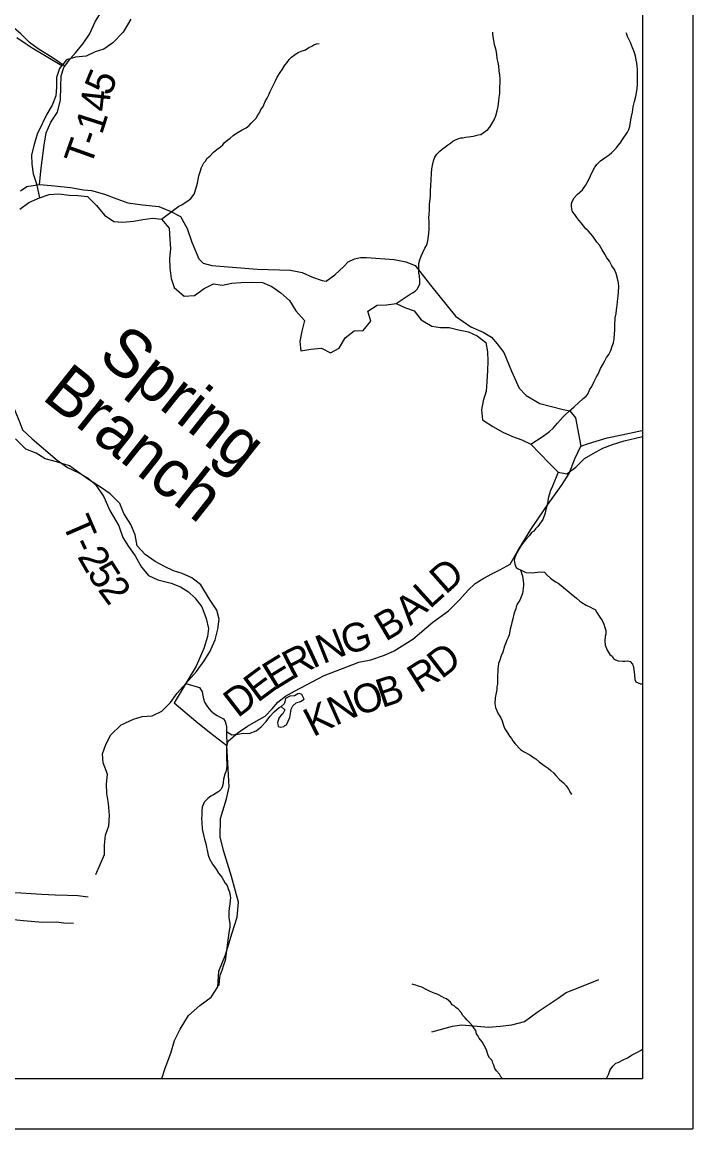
# Model space of a CAD drawing. Extents: x 0 to 34, y 0 to 22.
# Drawn here: x 7.671 to 9, y 14 to 16.191 of the extents above; entities that cross this region are included whole.
import ezdxf

# ---------------------------------------------------------------- set-up
doc = ezdxf.new("R2010")
doc.units = 0
for name, color, linetype in [('GM_X_County_Road', 7, 'Continuous'), ('GM_X_County_Road_Text', 7, 'Continuous'), ('GM_X_Major_River', 7, 'Continuous'), ('GM_X_Minor_Lake', 7, 'Continuous'), ('GM_X_Minor_River', 7, 'Continuous'), ('GM_X_Minor_River_Text', 7, 'Continuous'), ('GM_X_Township_Road', 7, 'Continuous'), ('GM_X_Township_Road_Text', 7, 'Continuous'), ('SH_Data', 7, 'Continuous')]:
    doc.layers.add(name, color=color, linetype=linetype)

msp = doc.modelspace()

# ---------------------------------------------------------------- linework, layer by layer
at = {"layer": 'GM_X_County_Road'}
for points in [[(7.668, 15.8575), (7.6806, 15.8662), (7.706, 15.87), (7.7288, 15.8681), (7.7672, 15.8643), (7.793, 15.8597), (7.8089, 15.8582), (7.8344, 15.851), (7.8587, 15.8415), (7.8807, 15.8339), (7.9099, 15.83), (7.9422, 15.8266), (7.9643, 15.8171), (7.9848, 15.8065), (7.9984, 15.7826), (8.0075, 15.7556), (8.0158, 15.7355), (8.0211, 15.7229), (8.0302, 15.7142), (8.047, 15.7093), (8.1366, 15.7024), (8.203, 15.7001), (8.2262, 15.6959), (8.2463, 15.6868), (8.2657, 15.6799), (8.2737, 15.6788), (8.2908, 15.691), (8.3083, 15.7077), (8.317, 15.7168), (8.3295, 15.7228), (8.3413, 15.7255), (8.3535, 15.7251), (8.4082, 15.7213), (8.4313, 15.7168), (8.4499, 15.7095), (8.4803, 15.6708), (8.5296, 15.6093), (8.5604, 15.588), (8.5847, 15.5774), (8.601, 15.5675), (8.6124, 15.5546), (8.6253, 15.5375), (8.6404, 15.5003), (8.6556, 15.4668), (8.6696, 15.4524), (8.6966, 15.4365), (8.7429, 15.4243), (8.7566, 15.4216), (8.7672, 15.408), (8.7778, 15.3521)], [(7.9479, 14.1), (7.9548, 14.1203), (7.9658, 14.1499), (7.9734, 14.1753), (7.9841, 14.1973), (8.0012, 14.2246), (8.0236, 14.2444), (8.0461, 14.2607), (8.059, 14.2812), (8.0613, 14.3123), (8.0742, 14.3446), (8.0872, 14.3883), (8.0971, 14.4194), (8.0998, 14.449), (8.0858, 14.4995), (8.0703, 14.5511), (8.0635, 14.5782), (8.0642, 14.6145), (8.0764, 14.6537), (8.0814, 14.6776), (8.0788, 14.7247), (8.0769, 14.7592), (8.0792, 14.7679), (8.0993, 14.785), (8.1179, 14.7975), (8.135, 14.8074), (8.1525, 14.8173), (8.1666, 14.8317), (8.178, 14.8446), (8.1928, 14.8571), (8.2111, 14.8666), (8.2472, 14.8856), (8.2696, 14.8974), (8.3144, 14.9152), (8.3383, 14.9243), (8.3619, 14.9288), (8.3889, 14.9383), (8.4086, 14.9467), (8.4291, 14.9596), (8.4455, 14.9695), (8.485, 15.0032), (8.5162, 15.0256), (8.5375, 15.0473), (8.5546, 15.067), (8.569, 15.0799), (8.5857, 15.0902), (8.6017, 15.0993), (8.6188, 15.1073), (8.6382, 15.1179), (8.653, 15.1445), (8.6793, 15.1866), (8.6945, 15.209), (8.7127, 15.2363), (8.7397, 15.2739), (8.755, 15.2975), (8.7664, 15.3267), (8.7778, 15.3521), (8.793, 15.3571), (8.8302, 15.3685), (8.8591, 15.3745), (8.8986, 15.3829), (8.9, 15.383)]]:
    msp.add_lwpolyline(points, dxfattribs=at)
at = {"layer": 'GM_X_Major_River'}
for points in [[(7.6666, 15.8213), (7.6848, 15.8341), (7.706, 15.8439), (7.725, 15.8499), (7.7439, 15.8514), (7.7643, 15.8491), (7.7817, 15.8483), (7.8006, 15.8459), (7.8188, 15.8284), (7.8346, 15.8094), (7.8527, 15.7965), (7.8701, 15.7957), (7.8928, 15.7971), (7.9103, 15.8009), (7.93, 15.8031), (7.9474, 15.8015), (7.9624, 15.7833), (7.9639, 15.7613), (7.9653, 15.7431), (7.963, 15.7226), (7.9637, 15.7052), (7.9667, 15.6839), (7.9727, 15.6657), (7.9923, 15.649), (8.0127, 15.6504), (8.0317, 15.664), (8.0507, 15.6731), (8.0681, 15.6708), (8.087, 15.6745), (8.1044, 15.676), (8.1249, 15.6767), (8.1476, 15.6758), (8.1657, 15.6682), (8.1838, 15.6553), (8.2012, 15.64), (8.2132, 15.6195), (8.2306, 15.6005), (8.2252, 15.5793), (8.2214, 15.5588), (8.2236, 15.5406), (8.2433, 15.5436), (8.2645, 15.5458), (8.2819, 15.5367), (8.2993, 15.5457), (8.3115, 15.5662), (8.3289, 15.5805), (8.3471, 15.5812), (8.3623, 15.5994), (8.3563, 15.6191), (8.3745, 15.6312), (8.3934, 15.6319), (8.4124, 15.6342)], [(8.4124, 15.6342), (8.4305, 15.6258), (8.4479, 15.6197), (8.4615, 15.6022), (8.4826, 15.5892), (8.5, 15.5869), (8.5174, 15.5869), (8.5356, 15.5823), (8.5553, 15.5784), (8.5726, 15.57), (8.59, 15.5571), (8.593, 15.5389), (8.5937, 15.5199), (8.5929, 15.5017), (8.592, 15.479), (8.5905, 15.4608), (8.5844, 15.4418), (8.5813, 15.4236), (8.5835, 15.4039), (8.6039, 15.391), (8.6235, 15.3795), (8.6424, 15.3711), (8.6613, 15.3643), (8.6787, 15.3559), (8.6968, 15.3376), (8.7157, 15.3178), (8.733, 15.3004), (8.7504, 15.2973), (8.7679, 15.3101), (8.7854, 15.3275), (8.8028, 15.3373), (8.8218, 15.3479), (8.8407, 15.3554), (8.8642, 15.3622), (8.8862, 15.3675), (8.9, 15.3709)]]:
    msp.add_lwpolyline(points, dxfattribs=at)
at = {"layer": 'GM_X_Minor_Lake'}
for points in [[(8.23, 14.8508), (8.2255, 14.8599), (8.2206, 14.8618), (8.2175, 14.8614), (8.2107, 14.8573), (8.2017, 14.8565), (8.1933, 14.852), (8.1914, 14.8455), (8.1903, 14.8417), (8.1846, 14.8364)], [(8.1846, 14.8364), (8.1918, 14.8296), (8.188, 14.822), (8.1854, 14.8198), (8.1808, 14.8148), (8.177, 14.8046), (8.1782, 14.797), (8.1835, 14.7952), (8.1895, 14.7967), (8.1918, 14.7989), (8.1948, 14.8001), (8.1982, 14.8073), (8.2013, 14.8145), (8.2035, 14.8262), (8.2043, 14.8311), (8.2077, 14.8376), (8.2141, 14.8436), (8.2228, 14.8463), (8.23, 14.8508)]]:
    msp.add_lwpolyline(points, dxfattribs=at)
at = {"layer": 'GM_X_Minor_River'}
for points in [[(7.8865, 16.1976), (7.8713, 16.1719), (7.8508, 16.1507), (7.8333, 16.1379), (7.8159, 16.1326), (7.7985, 16.1243), (7.7773, 16.1221), (7.7591, 16.1168), (7.7454, 16.0994), (7.7393, 16.082), (7.7393, 16.063), (7.7384, 16.0456), (7.7308, 16.0274), (7.7202, 16.0092), (7.711, 15.9903), (7.7011, 15.9698), (7.695, 15.9494), (7.6896, 15.9289), (7.6903, 15.91), (7.6933, 15.891), (7.7, 15.8712), (7.706, 15.8439)], [(7.75, 16.1052), (7.6911, 16.14), (7.6771, 16.1491), (7.6608, 16.1604)], [(8.4124, 15.6342), (8.4403, 15.6527), (8.4449, 15.6557), (8.4499, 15.659), (8.4541, 15.6627), (8.4564, 15.6673), (8.4592, 15.6733), (8.4593, 15.6801), (8.4583, 15.6889), (8.4573, 15.6953), (8.4571, 15.7022), (8.4573, 15.7136), (8.4593, 15.7211), (8.4621, 15.7279), (8.4652, 15.7351), (8.4692, 15.7441), (8.4723, 15.749), (8.4743, 15.7551), (8.4755, 15.7623), (8.4769, 15.7733), (8.4774, 15.782), (8.4775, 15.7888), (8.4773, 15.7968), (8.477, 15.8044), (8.4775, 15.8109), (8.4781, 15.82), (8.4786, 15.831), (8.4796, 15.8408), (8.4801, 15.848), (8.4806, 15.8575), (8.4808, 15.8674), (8.4814, 15.8792), (8.482, 15.8921), (8.4829, 15.9008), (8.4846, 15.911), (8.4862, 15.9171), (8.4886, 15.9239), (8.4929, 15.9302), (8.4987, 15.9358), (8.5041, 15.9403), (8.5083, 15.9433), (8.514, 15.9477), (8.5198, 15.9518), (8.5248, 15.9555), (8.5297, 15.9585), (8.5343, 15.9603), (8.5404, 15.9621), (8.5446, 15.9624), (8.5499, 15.9635), (8.5556, 15.9645), (8.5602, 15.9652), (8.5655, 15.9659), (8.5746, 15.968), (8.5803, 15.969), (8.5849, 15.972), (8.5895, 15.9757), (8.5941, 15.9787), (8.5976, 15.9836), (8.6019, 15.9899), (8.6066, 15.9982), (8.6094, 16.0062), (8.6122, 16.016), (8.6142, 16.0247), (8.6156, 16.0357), (8.6165, 16.0425), (8.6173, 16.0505), (8.6178, 16.0569), (8.6182, 16.0782), (8.6176, 16.0873), (8.6166, 16.0945), (8.6157, 16.1048), (8.6146, 16.1113), (8.6125, 16.1193), (8.6119, 16.1273), (8.6101, 16.1357), (8.608, 16.1444), (8.6052, 16.1582), (8.6042, 16.1631), (8.6039, 16.1677), (8.604, 16.1719)], [(8.8906, 16.0808), (8.8903, 16.0877), (8.8901, 16.0979), (8.8895, 16.104), (8.8892, 16.1101), (8.8878, 16.1162), (8.8868, 16.1215), (8.885, 16.1288), (8.8828, 16.1345), (8.8803, 16.1406), (8.8763, 16.151), (8.873, 16.1579), (8.8708, 16.1632), (8.869, 16.1678), (8.8679, 16.1705)], [(7.9474, 15.8015), (7.9816, 15.8268), (7.9877, 15.8297), (7.9942, 15.8342), (7.9996, 15.8379), (8.0058, 15.8423), (8.012, 15.851), (8.0163, 15.8634), (8.0188, 15.8729), (8.02, 15.8797), (8.0213, 15.8873), (8.0237, 15.8948), (8.0265, 15.9039), (8.0312, 15.9129), (8.0351, 15.917), (8.0374, 15.9212), (8.0436, 15.9268), (8.0502, 15.9339), (8.0571, 15.9394), (8.0644, 15.9446), (8.069, 15.9484), (8.0717, 15.9525), (8.0786, 15.9585), (8.0836, 15.9618), (8.0894, 15.967), (8.0963, 15.9715), (8.107, 15.9785), (8.115, 15.9825), (8.1212, 15.987), (8.125, 15.9915), (8.1289, 15.9956), (8.1358, 16.0023), (8.1378, 16.0065), (8.1417, 16.0117), (8.1441, 16.0185), (8.1479, 16.0234), (8.1503, 16.0275), (8.1531, 16.0355), (8.1566, 16.0411), (8.1597, 16.0475), (8.1625, 16.0543), (8.1688, 16.0663), (8.1723, 16.0739), (8.1766, 16.0822), (8.1825, 16.0916), (8.1871, 16.0983), (8.1918, 16.1066), (8.1965, 16.1118), (8.2, 16.1175), (8.205, 16.1219), (8.2127, 16.1283), (8.218, 16.1316), (8.2241, 16.1338), (8.2287, 16.1352), (8.2329, 16.1367), (8.2394, 16.1411), (8.2451, 16.1441), (8.2494, 16.1463), (8.2554, 16.1484), (8.2596, 16.1495)], [(8.6787, 15.3559), (8.7035, 15.3718), (8.7108, 15.377), (8.7162, 15.3811), (8.7235, 15.3874), (8.7316, 15.3976), (8.7424, 15.4095), (8.747, 15.4136), (8.7551, 15.4211), (8.7651, 15.4297), (8.7736, 15.4379), (8.7828, 15.4465), (8.7886, 15.4509), (8.7917, 15.455), (8.7957, 15.4645), (8.7991, 15.4686), (8.8035, 15.4788), (8.809, 15.4893), (8.8121, 15.4946), (8.8168, 15.5059), (8.8219, 15.5134), (8.8254, 15.5209), (8.829, 15.5273), (8.8336, 15.5333), (8.8372, 15.5413), (8.8404, 15.5499), (8.8427, 15.5564), (8.844, 15.5647), (8.8446, 15.5742), (8.8451, 15.5814), (8.8452, 15.5905), (8.8463, 15.6057), (8.8479, 15.6148), (8.8488, 15.622), (8.8497, 15.6265), (8.8501, 15.6307), (8.8506, 15.6386), (8.8515, 15.6439), (8.8519, 15.6489), (8.8528, 15.6572), (8.8534, 15.6671), (8.8524, 15.6754), (8.8507, 15.6838), (8.8478, 15.6938), (8.8449, 15.7014), (8.8397, 15.7091), (8.8346, 15.7179), (8.8294, 15.7248), (8.8254, 15.7321), (8.8206, 15.7405), (8.8151, 15.7498), (8.8099, 15.7559), (8.8058, 15.7617), (8.8018, 15.7678), (8.7973, 15.7732), (8.7925, 15.7782), (8.788, 15.7825), (8.7836, 15.7879), (8.7787, 15.794), (8.7739, 15.7991), (8.7702, 15.8048), (8.7662, 15.8106), (8.7617, 15.816), (8.7603, 15.8221), (8.7593, 15.8274), (8.7593, 15.8316), (8.7609, 15.8365), (8.7648, 15.8433), (8.771, 15.8504), (8.776, 15.8549), (8.7814, 15.8593), (8.7872, 15.868), (8.7923, 15.877), (8.7974, 15.8872), (8.8014, 15.8954), (8.8057, 15.9045), (8.8103, 15.9101), (8.8169, 15.9168), (8.8234, 15.9213), (8.828, 15.9246), (8.8341, 15.9287), (8.8395, 15.9332), (8.8434, 15.9373), (8.848, 15.9421), (8.8523, 15.9474), (8.8558, 15.9515), (8.8608, 15.9594), (8.8702, 15.9737), (8.8733, 15.9789), (8.8753, 15.985), (8.8761, 15.9892), (8.8774, 15.9979), (8.8787, 16.0047), (8.8803, 16.0134), (8.882, 16.0236), (8.8845, 16.0346), (8.8869, 16.044), (8.8882, 16.0516), (8.8895, 16.0603), (8.8904, 16.0687), (8.8906, 16.0808)], [(7.8176, 14.5036), (7.8344, 14.543), (7.8345, 14.5619), (7.8368, 14.5816), (7.8429, 14.5998), (7.8445, 14.6203), (7.8423, 14.6446), (7.8393, 14.6643), (7.8386, 14.6833), (7.8402, 14.7022), (7.8319, 14.725), (7.8305, 14.7424), (7.8374, 14.7614), (7.8473, 14.7803), (7.8678, 14.8), (7.892, 14.8113), (7.9094, 14.8165), (7.9291, 14.818), (7.9481, 14.827), (7.9655, 14.8444), (7.9785, 14.8626), (7.9959, 14.8822), (8.0165, 14.9057), (8.0317, 14.9269), (8.0431, 14.9443), (8.0537, 14.9685), (8.0591, 14.9897), (8.0614, 15.0095), (8.057, 15.0269), (8.0426, 15.0489), (8.0253, 15.0771), (8.0072, 15.0908), (7.9883, 15.0999), (7.9709, 15.1053), (7.9535, 15.1137), (7.9346, 15.1236), (7.915, 15.1373), (7.8992, 15.1548), (7.8954, 15.176), (7.8864, 15.1965), (7.8729, 15.2185), (7.8646, 15.2383), (7.8457, 15.2573), (7.8284, 15.2695), (7.8049, 15.2847), (7.7868, 15.2969), (7.7649, 15.3129), (7.7392, 15.3205), (7.7173, 15.3267), (7.6991, 15.3381), (7.6787, 15.3457), (7.6583, 15.3663)], [(8.733, 15.3004), (8.7218, 15.2724), (8.7183, 15.2641), (8.7155, 15.2558), (8.7134, 15.2479), (8.7121, 15.238), (8.7081, 15.2236), (8.7076, 15.2191), (8.7029, 15.2066), (8.6994, 15.2021), (8.6932, 15.1931), (8.6881, 15.1879), (8.6847, 15.1838), (8.6801, 15.1808), (8.6766, 15.1752), (8.6692, 15.1673), (8.6626, 15.1591), (8.6568, 15.1501), (8.6521, 15.1418), (8.6494, 15.1361), (8.6474, 15.1312), (8.6458, 15.1263), (8.6471, 15.1179), (8.6501, 15.1118), (8.6542, 15.1087), (8.6587, 15.1071), (8.6639, 15.104), (8.6688, 15.1016), (8.6817, 15.1007), (8.6923, 15.1024), (8.701, 15.103), (8.706, 15.1025), (8.7112, 15.0967), (8.7179, 15.0902), (8.728, 15.0832), (8.7332, 15.0804), (8.7388, 15.0758), (8.7474, 15.0684), (8.7541, 15.0637), (8.7597, 15.0591), (8.7653, 15.0541), (8.7698, 15.051), (8.7762, 15.0452), (8.7803, 15.0424), (8.7889, 15.037), (8.7972, 15.033), (8.802, 15.0303), (8.8065, 15.0283), (8.8099, 15.0226), (8.8146, 15.0153), (8.8202, 15.0064), (8.8235, 14.9996), (8.8256, 14.9927), (8.8274, 14.9866), (8.8273, 14.9794), (8.8264, 14.9748), (8.8259, 14.9661), (8.8265, 14.9577), (8.8301, 14.9482), (8.8353, 14.9394), (8.8398, 14.9359), (8.8427, 14.9313), (8.8468, 14.9285), (8.8517, 14.9265), (8.8612, 14.926), (8.8654, 14.9263), (8.8714, 14.927), (8.8756, 14.9254), (8.8804, 14.9204), (8.8826, 14.915), (8.8842, 14.8983), (8.8848, 14.8895), (8.887, 14.8853), (8.8915, 14.883), (8.8964, 14.8814), (8.9, 14.881)], [(8.6587, 15.1071), (8.6626, 15.0941), (8.6629, 15.0896), (8.664, 15.085), (8.6647, 15.0801), (8.6646, 15.0759), (8.6641, 15.0709), (8.6624, 15.0603), (8.6573, 15.0471), (8.6522, 15.0392), (8.6502, 15.034), (8.6494, 15.0298), (8.6466, 15.0234), (8.6454, 15.0192), (8.6433, 15.0098), (8.6417, 15.003), (8.6401, 14.9965), (8.6384, 14.9897), (8.6363, 14.978), (8.6344, 14.9731), (8.6316, 14.9674), (8.6288, 14.9603), (8.6269, 14.9557), (8.6236, 14.944), (8.6205, 14.9369), (8.6177, 14.9278), (8.6149, 14.9218), (8.6144, 14.9153), (8.6139, 14.9108), (8.6138, 14.9047), (8.6133, 14.8982), (8.613, 14.8804), (8.6118, 14.8751), (8.6117, 14.8694), (8.6101, 14.8634), (8.6084, 14.8535), (8.6078, 14.8425), (8.6092, 14.8345), (8.6143, 14.8219), (8.6187, 14.815), (8.622, 14.8081), (8.6249, 14.7989), (8.6278, 14.7921), (8.6329, 14.784), (8.637, 14.7778), (8.6407, 14.7732), (8.6436, 14.7682), (8.6477, 14.7625), (8.6585, 14.7513), (8.6648, 14.747), (8.6769, 14.7407), (8.6821, 14.7368), (8.6888, 14.7326), (8.6955, 14.7267), (8.7053, 14.7194), (8.7131, 14.7143), (8.7187, 14.7096), (8.7243, 14.7046), (8.7284, 14.6996), (8.7358, 14.6919), (8.7437, 14.6853), (8.7493, 14.6795), (8.7537, 14.6726), (8.7577, 14.6653), (8.7595, 14.662)], [(7.9959, 14.8822), (8.0224, 14.874), (8.0279, 14.8656), (8.0293, 14.8583), (8.0303, 14.8518), (8.0329, 14.845), (8.0388, 14.8358), (8.0451, 14.8277), (8.0525, 14.8215), (8.0578, 14.8187), (8.0623, 14.8156), (8.0705, 14.8117), (8.0735, 14.8067), (8.0749, 14.8017), (8.076, 14.7964), (8.0763, 14.7918), (8.0762, 14.7869), (8.0764, 14.7808), (8.0763, 14.7747), (8.0766, 14.7687), (8.0762, 14.7474), (8.0765, 14.7398), (8.0763, 14.7314), (8.0766, 14.7235), (8.0769, 14.7189), (8.0764, 14.7132), (8.0751, 14.7068), (8.0728, 14.7023), (8.0703, 14.6924), (8.0698, 14.6856), (8.069, 14.6811), (8.0674, 14.6765), (8.0651, 14.672), (8.0608, 14.6683), (8.0555, 14.6646), (8.0501, 14.6616), (8.0451, 14.6591), (8.039, 14.6542), (8.032, 14.6468), (8.0277, 14.637), (8.0272, 14.6297), (8.027, 14.6203), (8.0269, 14.6153), (8.0275, 14.6062), (8.0281, 14.5944), (8.0291, 14.5876), (8.0312, 14.5792), (8.0323, 14.5738), (8.0341, 14.5689), (8.0359, 14.5624), (8.0365, 14.5574), (8.0376, 14.5521), (8.04, 14.5418), (8.0426, 14.5349), (8.0484, 14.5242), (8.0555, 14.5142), (8.0606, 14.5061), (8.0669, 14.4981), (8.0702, 14.4927), (8.0735, 14.4866), (8.0772, 14.4819), (8.0798, 14.4754), (8.0816, 14.4709), (8.0826, 14.4659), (8.0837, 14.4617), (8.084, 14.4575), (8.0835, 14.4526), (8.0827, 14.4458), (8.0814, 14.4371), (8.0809, 14.4299), (8.0808, 14.4242), (8.081, 14.4177), (8.0824, 14.4108), (8.0827, 14.4063), (8.0826, 14.3994), (8.0817, 14.3926), (8.0805, 14.3881)], [(8.0762, 14.7868), (8.087, 14.78), (8.0983, 14.7815), (8.11, 14.7834), (8.1214, 14.7827), (8.135, 14.788), (8.1449, 14.7963), (8.1547, 14.8065), (8.1623, 14.8164), (8.1706, 14.8258), (8.1804, 14.8345), (8.1846, 14.8364)], [(8.0805, 14.3881), (8.0736, 14.3334), (8.0705, 14.3239), (8.0671, 14.3137), (8.063, 14.3039), (8.0618, 14.294), (8.0607, 14.2838), (8.0603, 14.2842)], [(8.6228, 14.1), (8.6198, 14.1033), (8.6168, 14.1083), (8.6113, 14.1149), (8.608, 14.1195), (8.6054, 14.126), (8.6036, 14.1298), (8.6025, 14.1351), (8.597, 14.1409), (8.5944, 14.1455), (8.5922, 14.152), (8.5912, 14.1566), (8.5868, 14.1654), (8.5827, 14.1723), (8.5794, 14.1762), (8.5768, 14.1796), (8.5746, 14.1838), (8.5717, 14.1884), (8.5699, 14.1945), (8.5677, 14.1984), (8.5625, 14.2049), (8.5573, 14.2103), (8.5528, 14.2153), (8.5491, 14.2196), (8.5439, 14.2254), (8.5417, 14.2296), (8.535, 14.2369), (8.5302, 14.24), (8.5272, 14.2435), (8.5234, 14.2458), (8.5201, 14.2512), (8.5119, 14.2574), (8.5078, 14.259), (8.5036, 14.2617), (8.4973, 14.2645), (8.4935, 14.2668), (8.4875, 14.2688), (8.4841, 14.27), (8.4785, 14.2724), (8.4728, 14.2752), (8.4631, 14.2803), (8.4582, 14.2822), (8.4548, 14.2834), (8.451, 14.2846), (8.4476, 14.2855), (8.4439, 14.2863)], [(8.8285, 14.1), (8.8296, 14.101), (8.8331, 14.1078), (8.8363, 14.1168), (8.8414, 14.1243), (8.8471, 14.1299), (8.8517, 14.1317), (8.862, 14.1365), (8.8708, 14.1405), (8.8796, 14.1468), (8.8888, 14.1509), (8.8965, 14.1553), (8.9, 14.1576)]]:
    msp.add_lwpolyline(points, dxfattribs=at)
at = {"layer": 'GM_X_Township_Road'}
for points in [[(7.7559, 16.1046), (7.7328, 16.1199), (7.7028, 16.1385), (7.6858, 16.1514), (7.6687, 16.1685), (7.6558, 16.1795), (7.6379, 16.1924), (7.6266, 16.2015), (7.6137, 16.2171), (7.603, 16.2388), (7.5913, 16.2642), (7.5784, 16.2795), (7.5746, 16.284), (7.5611, 16.2941), (7.5484, 16.3037), (7.5441, 16.3069)], [(7.706, 15.87), (7.7091, 15.9026), (7.7148, 15.9478), (7.719, 15.9721), (7.7285, 15.9934), (7.7411, 16.0135), (7.7476, 16.0374), (7.7483, 16.064), (7.7484, 16.0849), (7.7537, 16.1016), (7.7559, 16.1046), (7.7663, 16.1187), (7.7773, 16.1309), (7.7921, 16.1491), (7.805, 16.1677), (7.8168, 16.1931), (7.8281, 16.2111)], [(7.612, 15.4947), (7.6267, 15.4872), (7.6328, 15.4648), (7.646, 15.444), (7.6559, 15.4242), (7.6676, 15.3965), (7.6718, 15.3843), (7.6915, 15.3661), (7.7405, 15.3239), (7.7614, 15.3095), (7.7826, 15.2996), (7.8024, 15.2882), (7.8157, 15.2758)], [(7.8157, 15.2758), (7.8179, 15.2738), (7.8335, 15.2514), (7.8452, 15.2244), (7.8627, 15.1944), (7.8706, 15.1712), (7.882, 15.1534), (7.8953, 15.1344), (7.9078, 15.112), (7.9218, 15.0957), (7.9401, 15.0869), (7.9666, 15.0805), (7.9852, 15.0732), (8.0012, 15.0634), (8.0137, 15.0516), (8.0274, 15.0337), (8.0361, 15.0106), (8.0406, 14.9908), (8.0387, 14.9749), (8.0315, 14.951), (8.0163, 14.916), (7.9965, 14.883), (7.9725, 14.8439), (8.0154, 14.8074), (8.0427, 14.7858), (8.0769, 14.7592)], [(7.5997, 14.4488), (7.6062, 14.4561), (7.6169, 14.4645), (7.6257, 14.4683), (7.6337, 14.4691), (7.6689, 14.4672), (7.6895, 14.466), (7.7102, 14.4645), (7.7366, 14.4633), (7.7614, 14.4626), (7.7818, 14.4621), (7.8021, 14.4597)], [(7.6544, 14.4148), (7.6739, 14.4125), (7.7117, 14.409), (7.7389, 14.4098), (7.7538, 14.4083), (7.7729, 14.4075)], [(8.4827, 14.192), (8.5241, 14.2035), (8.5425, 14.2058), (8.5953, 14.2013), (8.6183, 14.2036), (8.6413, 14.2059), (8.6665, 14.2128), (8.6918, 14.2311), (8.7332, 14.2587), (8.7493, 14.2702), (8.7791, 14.2817), (8.8136, 14.2955)]]:
    msp.add_lwpolyline(points, dxfattribs=at)
at = {"layer": 'SH_Data'}
for p, q in [((9, 21), (9, 14)), ((8.9, 20.9), (8.9, 14.1)), ((2.1, 14.1), (8.9, 14.1)), ((2, 14), (9, 14))]:
    msp.add_line(p, q, dxfattribs=at)

# ---------------------------------------------------------------- texts
at = {"layer": 'GM_X_County_Road_Text'}
for s, rotation, p in [('D', 41.6921, (8.5103, 15.0567)), ('L', 42.207, (8.4789, 15.0282)), ('A', 41.1698, (8.4404, 14.9946)), ('B', 30.7437, (8.3912, 14.9641)), ('N', 21.68, (8.2673, 14.92)), ('G', 16.3587, (8.3124, 14.938)), ('I', 25.0307, (8.2469, 14.9105)), ('R', 27.388, (8.206, 14.8893)), ('D', 37.5563, (8.5019, 14.8895)), ('E', 31.6756, (8.1709, 14.8675)), ('R', 32.4507, (8.458, 14.8613)), ('E', 36.6102, (8.1378, 14.8429)), ('O', 18.0223, (8.3361, 14.8173)), ('B', 18.555, (8.3842, 14.833)), ('D', 37.7048, (8.0985, 14.8125)), ('N', 23.9095, (8.2918, 14.7976)), ('K', 26.9397, (8.248, 14.7753))]:
    msp.add_text(s, height=0.0568, rotation=rotation, dxfattribs=at).set_placement(p)
at = {"layer": 'GM_X_Minor_River_Text'}
for s, rotation, p in [('Spring', 321.4993, (7.8187, 15.5249)), ('Branch', 321.4987, (7.7081, 15.4466))]:
    msp.add_text(s, height=0.09468, rotation=rotation, dxfattribs=at).set_placement(p)
at = {"layer": 'GM_X_Township_Road_Text'}
for s, rotation, p in [('5', 67.6091, (7.8455, 16.0434)), ('4', 83.7529, (7.8427, 16.0127)), ('1', 72.1992, (7.8294, 15.9672)), ('T', 70.2944, (7.8067, 15.9032)), ('-', 70.5632, (7.8211, 15.9435)), ('T', 293.4812, (7.7498, 15.1994)), ('-', 295.475, (7.7676, 15.1585)), ('2', 299.7826, (7.7798, 15.1333)), ('5', 302.523, (7.7988, 15.1004)), ('2', 306.3992, (7.8199, 15.0674))]:
    msp.add_text(s, height=0.0568, rotation=rotation, dxfattribs=at).set_placement(p)

doc.saveas('drawing.dxf')
